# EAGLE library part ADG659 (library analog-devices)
+3 V/+5 V/±5 V CMOS 4-Channel Analog Multiplexers Source: ADG658_659.pdf
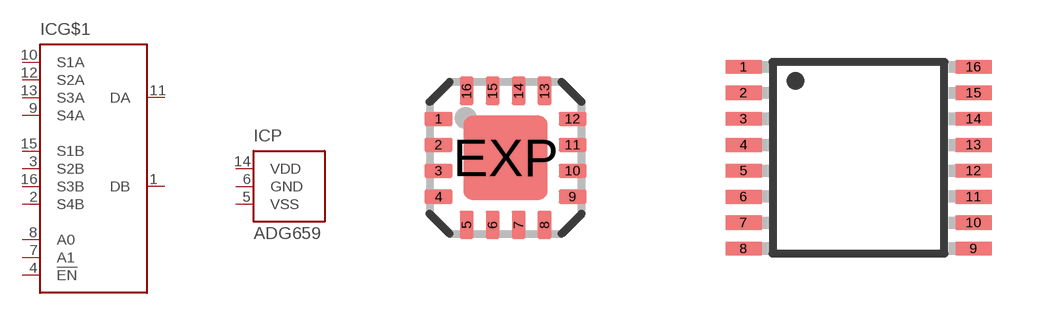
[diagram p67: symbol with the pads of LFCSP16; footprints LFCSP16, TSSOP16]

Designator prefix IC; gates G$1=ADG659 P=PWR-VSS_GND_VDD

## ADG659CP (MPN: ADG659YCPZ; OC_FARNELL: unknown; OC_NEWARK: 74R5857)  [LFCSP16]
1  G$1:DB
2  G$1:S4B
3  G$1:S2B
4  G$1:!EN  in
5  P:VSS  pwr
6  P:GND  pwr
7  G$1:A1  in
8  G$1:A0  in
9  G$1:S4A
10  G$1:S1A
11  G$1:DA
12  G$1:S2A
13  G$1:S3A
14  P:VDD  pwr
15  G$1:S1B
16  G$1:S3B

## ADG659RU (MF: ALTERA CORPORATION; MPN: ADG659YRU-REEL7; OC_FARNELL: 1438948; OC_NEWARK: 50H3058)  [TSSOP16]
1  G$1:S1B
2  G$1:S3B
3  G$1:DB
4  G$1:S4B
5  G$1:S2B
6  G$1:!EN  in
7  P:VSS  pwr
8  P:GND  pwr
9  G$1:A1  in
10  G$1:A0  in
11  G$1:S4A
12  G$1:S1A
13  G$1:DA
14  G$1:S2A
15  G$1:S3A
16  P:VDD  pwr

## ADG659RQ (MF: ALTERA CORPORATION; MPN: ADG659YRQ; OC_FARNELL: 1465237; OC_NEWARK: 59K1460)  [QSOP16]
Pads as for TSSOP16

## Footprint LFCSP16 (pad centres in mm)
16-Terminal Leadless Frame Chip Scale Package [LFCSP] (CP) Source: Analog Devices .. 780914713ADD8704_0.pdf
smd 0.7 x 0.35: 1 -1.675,0.975; 2 -1.675,0.325; 3 -1.675,-0.325; 4 -1.675,-0.975; 9 1.675,-0.975; 10 1.675,-0.325; 11 1.675,0.325; 12 1.675,0.975
smd 0.35 x 0.7: 5 -0.975,-1.675; 6 -0.325,-1.675; 7 0.325,-1.675; 8 0.975,-1.675; 13 0.975,1.675; 14 0.325,1.675; 15 -0.325,1.675; 16 -0.975,1.675
smd 2.1 x 2.1: EXP 0,0

## Footprint TSSOP16 (pad centres in mm)
16-Lead Thin Shrink Small Outline Package [TSSOP] (RU-16) Source: 8x ADG1408_1409.pdf
smd 0.9 x 0.35: 1 -2.875,2.275; 2 -2.875,1.625; 3 -2.875,0.975; 4 -2.875,0.325; 5 -2.875,-0.325; 6 -2.875,-0.975; 7 -2.875,-1.625; 8 -2.875,-2.275; 9 2.875,-2.275; 10 2.875,-1.625; 11 2.875,-0.975; 12 2.875,-0.325; 13 2.875,0.325; 14 2.875,0.975; 15 2.875,1.625; 16 2.875,2.275

## Footprint QSOP16 (pad centres in mm)
16-Lead Shrink Small Outline Package QSOP (RQ-16) Source: ADG658_659.pdf
smd 0.381 x 1.27: 1 -2.223,-2.6; 2 -1.587,-2.6; 3 -0.953,-2.6; 4 -0.318,-2.6; 5 0.318,-2.6; 6 0.953,-2.6; 7 1.587,-2.6; 8 2.223,-2.6; 9 2.223,2.6; 10 1.587,2.6; 11 0.953,2.6; 12 0.318,2.6; 13 -0.318,2.6; 14 -0.953,2.6; 15 -1.587,2.6; 16 -2.223,2.6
